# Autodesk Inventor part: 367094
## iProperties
Created: 2006-08
Part Number: 367094
Material: 8.8 vz
Description: Sechskantschraube
Vendor: Autodesk Inc.
Document SubType Name: Modeling
Standard: DIN 933
Designer: I.Baliuc
Standards Organization: DIN
Language: de-DE
Size Designation: M12 x 35
Categories: <MemberInstance Version="R10.0.0"><Categories><Category DisplayName="Schrauben" InternalName="e4da775c-781d-43d5-af7c-5136215cf5a6" Mnemonic="FSTN"><Category Di
Density: 7.85 g/cm^3
Mass: 48.2476 g
Surface Area: 23.9819 cm^2
Volume: 6.14619 cm^3
Author: T.Messerschmitt
Comments: DIN 933 - M12 x 35
Revision Number: 367094
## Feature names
1. Körper [Revolution]
2. Kopf [Extrusion]
3. Fase1 [Revolution]
4. Fase2 [Chamfer]
